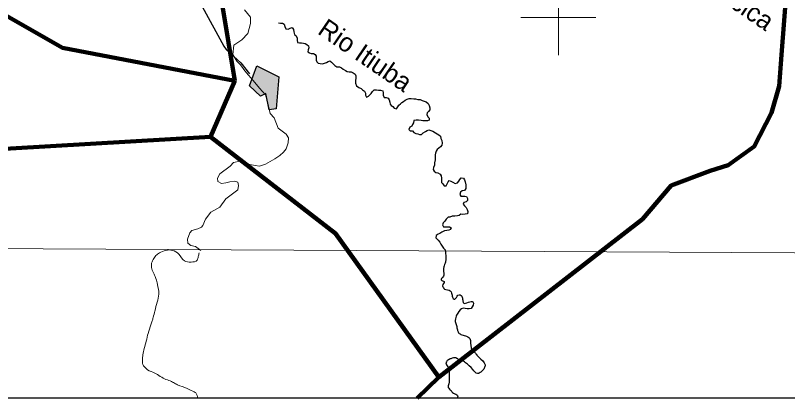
# Model space of a CAD drawing. Extents: x -1643653 to 4543381, y 1624270 to 13878484.
# Drawn here: x 735516 to 756116, y 8889723 to 8900056 of the extents above; entities that cross this region are included whole.
import ezdxf
from ezdxf.enums import TextEntityAlignment as Align

# ---------------------------------------------------------------- set-up
doc = ezdxf.new("R2010")
doc.units = 0
doc.header["$LTSCALE"] = 200
for name, color, linetype, lineweight in [('1', 7, 'Continuous', 13), ('12', 7, 'Continuous', 25), ('14', 7, 'Continuous', 13), ('2', 7, 'Continuous', 13), ('21', 7, 'Continuous', 25), ('24', 7, 'Continuous', 25), ('3', 7, 'Continuous', 13), ('57', 7, 'Continuous', 13), ('58', 7, 'Continuous', 13), ('60', 7, 'Continuous', 13), ('9', 7, 'Continuous', 90)]:
    doc.layers.add(name, color=color, linetype=linetype, lineweight=lineweight)
doc.layers.add('49', color=7, linetype='Continuous')

msp = doc.modelspace()

# ---------------------------------------------------------------- hatches: boundary and pattern name
at = {"layer": '21'}
msp.add_hatch(color=256, dxfattribs=at).paths.add_polyline_path([(741953.3, 8898708.5), (742539, 8898421), (742473.5, 8897565.2), (742282.6, 8897532.8), (742195.4, 8897971), (742053.9, 8897898.6), (741759, 8898176.9)])

# ---------------------------------------------------------------- linework, layer by layer
at = {"layer": '1'}
msp.add_lwpolyline([(564751.7, 8894587.5), (664411.9, 8894209.9), (791388.5, 8893536.2)], dxfattribs=at)
at = {"layer": '12'}
msp.add_lwpolyline([(746519.8, 8913147), (744583.5, 8912890.8), (744456, 8912865.6), (744221.3, 8912764.1), (744164.9, 8912662.3), (738981.9, 8906574.2), (738945.9, 8906472.4), (740401.6, 8900591.2), (740457, 8900407.7), (740497.3, 8900290.4), (741074.2, 8899240), (741140.1, 8899143.1), (741531, 8898790.9), (741761.4, 8898500.5)], dxfattribs=at)
at = {"layer": '14'}
msp.add_lwpolyline([(740463, 8893777.9), (740392, 8893831.3), (740315.8, 8893892.6), (740193.7, 8893918.3), (740112.4, 8893979.6), (740107.7, 8894081.4), (740164.3, 8894249.4), (740225.7, 8894315.6), (740378.7, 8894361.1), (740480.7, 8894401.7), (740516.6, 8894447.5), (740588.5, 8894620.5), (740731.8, 8894808.8), (740966.7, 8894940.8), (741130.5, 8895164.6), (741309.3, 8895291.6), (741447.2, 8895398.4), (741468, 8895515.5), (741453.1, 8895602.1), (741371.7, 8895632.8), (741234.1, 8895612.7), (741132.1, 8895587.4), (741009.7, 8895567.3), (740918.2, 8895623.5), (740908.4, 8895710.1), (740969.9, 8895827.1), (741245.8, 8896030.4), (741332.7, 8896127), (741501, 8896162.4), (741587.4, 8896116.4), (741658.7, 8896111.1), (741765.6, 8896075.3), (741908.1, 8896049.6), (742030.3, 8896034.1), (742188.4, 8896089.8), (742438.6, 8896232), (742566.2, 8896313.2), (742668.5, 8896409.8), (742740.1, 8896496.3), (742791.7, 8896659.2), (742802.3, 8896786.6), (742741.6, 8896883.4), (742523.1, 8897046.9), (742417.1, 8897322.1), (742310.6, 8897439.5), (742250.5, 8897714.7), (742190.2, 8897938.9), (742027.8, 8898112.4), (741855.3, 8898316.5), (741733.6, 8898464.5), (741637.2, 8898581.8), (741520.6, 8898734.9), (741424.2, 8898831.8), (741312.8, 8899015.4), (741344.3, 8899265), (741558.7, 8899402.1), (741717.3, 8899569.9), (741784.5, 8899839.8), (741790.2, 8900007.9), (741627.9, 8900201.8)], dxfattribs=at)
msp.add_spline([(740417.8, 8893718), (740395, 8893617.9), (740366.3, 8893527), (740201.3, 8893471.8), (740024.2, 8893508.9), (739877.2, 8893682.8), (739707.5, 8893786.1), (739358.5, 8893717.2), (739264.2, 8893644.1), (739189.2, 8893539.6), (739143.8, 8893408.5), (739155.2, 8893295.7), (739216.5, 8893150.5), (739263.3, 8893031.3), (739303.8, 8892876.6), (739340.8, 8892619.9), (739297.6, 8892401.9), (739233.3, 8892164.3), (739191.8, 8891997.3), (739163, 8891901.3), (739128.9, 8891800.4), (739054.6, 8891568.2), (739006.8, 8891365.7), (738954.1, 8891168.5), (738917.5, 8890996.2), (738902.9, 8890869.1), (738913.8, 8890741), (738932.9, 8890704.5), (739041.4, 8890598.4), (739232.1, 8890509.7), (739532.1, 8890340.4), (739683, 8890283.8), (739782.9, 8890223.9), (739838, 8890196.4), (740094.7, 8890100.1), (740245.1, 8890028.2), (740325, 8889979.3), (740376.2, 8889839.6), (740376.7, 8889836.8)], degree=3, dxfattribs=at)
at = {"layer": '2'}
for p, q in [((750000, 8899000), (750000, 8901000)), ((749000, 8900000), (751000, 8900000))]:
    msp.add_line(p, q, dxfattribs=at)
at = {"layer": '21'}
msp.add_lwpolyline([(741953.3, 8898708.5), (742539, 8898421), (742473.5, 8897565.2), (742282.6, 8897532.8), (742195.4, 8897971), (742053.9, 8897898.6), (741759, 8898176.9)], close=True, dxfattribs=at)
at = {"layer": '24'}
for points in [[(742537.4, 8899861.4), (742586, 8899849), (742636.8, 8899848.6), (742682.4, 8899822.9), (742702.3, 8899761.6), (742732.4, 8899695.2), (742793.4, 8899689.7), (742844.5, 8899719.9), (742900.5, 8899729.8), (742935.7, 8899678.6), (742945.5, 8899617.4), (742960.3, 8899551.1), (743005.8, 8899510.1), (743035.9, 8899453.8), (743035.5, 8899392.7), (743045.2, 8899331.5), (743096, 8899321), (743146.9, 8899320.7), (743197.7, 8899315.3), (743248.5, 8899304.8), (743294.1, 8899284.1), (743334.5, 8899243.1), (743344.3, 8899187), (743323.6, 8899136.2), (743318.2, 8899085.3), (743358.7, 8899054.4), (743409.4, 8899038.8), (743470.5, 8899038.4), (743516.1, 8899017.8), (743536.1, 8898971.8), (743535.8, 8898920.9), (743535.4, 8898864.8), (743560.5, 8898813.8), (743595.8, 8898777.9), (743646.7, 8898772.4), (743707.7, 8898767), (743763.7, 8898781.9), (743814.7, 8898796.8), (743855.6, 8898827.1), (743906.5, 8898842.1), (743947, 8898811.3), (743982.3, 8898770.3), (744032.9, 8898724.1), (744093.6, 8898683), (744159.7, 8898682.6), (744210.5, 8898661.9), (744261, 8898620.8), (744321.8, 8898584.7), (744367.5, 8898564.1), (744418.2, 8898548.5), (744474.2, 8898548.1), (744530, 8898527.4), (744580.6, 8898491.4), (744595.5, 8898440.3), (744595.1, 8898379.2), (744589.6, 8898318.1), (744584, 8898251.9), (744619.1, 8898180.4), (744679.8, 8898129.1), (744735.6, 8898103.3), (744776.1, 8898072.4), (744831.7, 8898031.3), (744851.8, 8897985.3), (744851.4, 8897929.3), (744881.5, 8897873.1), (744932.6, 8897903.3), (744968.4, 8897938.8), (745009.3, 8897974.2), (745040.2, 8898024.9), (745086.3, 8898070.4), (745147.3, 8898070.1), (745203.2, 8898064.6), (745259.2, 8898064.2), (745315, 8898043.5), (745329.9, 8897992.5), (745329.5, 8897931.3), (745354.5, 8897870.1), (745405.3, 8897869.7), (745456, 8897843.9), (745486.3, 8897803), (745506.2, 8897741.7), (745510.9, 8897690.8), (745541.2, 8897649.8), (745586.8, 8897624.1), (745622.1, 8897583.1), (745677.9, 8897562.4), (745713.9, 8897618.2), (745744.7, 8897663.8), (745785.6, 8897699.2), (745821.5, 8897734.6), (745872.5, 8897759.8), (745913.5, 8897795.2), (745964.5, 8897820.3), (746020.5, 8897835.2), (746076.5, 8897834.9), (746142.6, 8897834.4), (746193.4, 8897829), (746254.3, 8897808.3), (746315.3, 8897807.9), (746371.1, 8897782), (746421.9, 8897766.4)], [(746421.9, 8897766.4), (746477.7, 8897750.8), (746523.2, 8897709.8), (746553.3, 8897648.4), (746573.3, 8897592.3), (746567.8, 8897536.3), (746537, 8897495.7), (746501.2, 8897460.3), (746495.7, 8897409.4), (746520.8, 8897353.2), (746556.1, 8897312.2), (746549.6, 8897261.7), (746504.8, 8897246.3), (746443.7, 8897246.7), (746387.8, 8897247.1), (746336.9, 8897247.4), (746265.8, 8897258.1), (746209.9, 8897263.5), (746148.8, 8897248.6), (746133.1, 8897192.7), (746112.4, 8897141.9), (746091.8, 8897096.2), (746035.7, 8897076.2), (746009.8, 8897015.2), (746050.3, 8896979.3), (746106.2, 8896978.9), (746146.5, 8896927.7), (746197.2, 8896901.9), (746248, 8896891.4), (746298.8, 8896880.9), (746349.7, 8896880.6), (746390.6, 8896921.1), (746451.9, 8896956.3), (746497.9, 8896981.5), (746548.9, 8897006.6), (746599.6, 8896985.9), (746655.5, 8896970.3), (746726.3, 8896918.9), (746812.5, 8896872.5), (746857.9, 8896831.5), (746867.7, 8896770.3), (746892.7, 8896714.1), (746897.4, 8896647.8), (746891.9, 8896596.9), (746856, 8896546.2), (746815.1, 8896510.8), (746764, 8896480.6), (746738.2, 8896434.9), (746722.6, 8896384.1), (746717.2, 8896333.2), (746716.7, 8896261.9), (746711.2, 8896200.8), (746695.4, 8896119.4), (746695, 8896058.2), (746669.1, 8895997.3), (746663.6, 8895941.3), (746688.8, 8895895.3), (746729.2, 8895864.4), (746785.1, 8895853.9), (746845.9, 8895817.9), (746871, 8895771.9), (746880.8, 8895710.7), (746880.3, 8895649.5), (746885.1, 8895598.6), (746915.3, 8895557.6), (746955.7, 8895511.5), (747011.6, 8895511.2), (747037.4, 8895556.8), (747058.1, 8895612.8), (747088.9, 8895653.3), (747134.5, 8895632.6), (747185.2, 8895601.7), (747251.1, 8895565.7), (747312.2, 8895585.7), (747343.1, 8895631.3), (747373.9, 8895676.9), (747404.7, 8895717.5), (747465.7, 8895712), (747495.9, 8895671.1), (747515.9, 8895614.9), (747530.6, 8895538.4), (747530.2, 8895487.5), (747529.9, 8895436.5), (747493.9, 8895380.7), (747432.8, 8895370.9), (747391.9, 8895335.5), (747371.1, 8895274.5), (747401.3, 8895233.6), (747452.2, 8895228.2), (747503, 8895227.8), (747553.9, 8895222.4), (747573.8, 8895166.3), (747578.6, 8895115.3), (747537.7, 8895085), (747481.5, 8895059.9), (747460.9, 8895014.2), (747496.2, 8894978.3), (747541.7, 8894932.2), (747566.7, 8894876), (747586.7, 8894819.8), (747576.1, 8894763.8)], [(747576.1, 8894763.8), (747515, 8894748.9), (747453.9, 8894739.2), (747398, 8894749.7), (747357.1, 8894714.3), (747306.2, 8894704.4), (747234.9, 8894699.8), (747168.8, 8894695.1), (747107.6, 8894675.2), (747056.7, 8894670.4), (747005.5, 8894614.7), (746969.5, 8894569.1), (746928.5, 8894518.4), (746907.8, 8894462.5), (746937.9, 8894411.4), (746988.8, 8894411), (747039.7, 8894410.7), (747095.6, 8894415.4), (747141.2, 8894389.7), (747120.6, 8894344), (747074.7, 8894323.9), (747023.7, 8894314), (746962.6, 8894304.2), (746891.2, 8894274.1), (746840.1, 8894233.7), (746794.2, 8894213.6), (746738, 8894183.4), (746732.5, 8894117.2), (746793.1, 8894055.7), (746838.5, 8894004.5), (746868.6, 8893948.3), (746903.9, 8893897.1), (746934.1, 8893846), (746974.5, 8893805), (746979.5, 8893799.8)]]:
    msp.add_lwpolyline(points, dxfattribs=at)
msp.add_spline([(746979.5, 8893799.8), (746986.5, 8893472.8), (746946.2, 8893341.5), (746940.6, 8893178.3), (746921.6, 8893071.8), (746873.1, 8892996.9), (746953.2, 8892953.1), (746908.6, 8892842.4), (746932.2, 8892790.5), (746966.7, 8892753.5), (747117.8, 8892702), (747151.5, 8892644.6), (747178.3, 8892536.3), (747217.1, 8892478.7), (747258.7, 8892502.7), (747285.1, 8892527.3), (747322.8, 8892587.2), (747384.3, 8892595.2), (747442.4, 8892506.2), (747459.4, 8892408.6), (747468.7, 8892382.7), (747601.9, 8892403.3), (747719.4, 8892409.2), (747672.7, 8892237.3), (747458.7, 8892240.1), (747316.6, 8892112.5), (747261.6, 8891997.1), (747248.6, 8891915.8), (747270.3, 8891807.8), (747301.9, 8891689.2), (747324.6, 8891606.6), (747398.8, 8891542.6), (747519.9, 8891507.5), (747634.7, 8891436.9), (747660.9, 8891308.3), (747729.8, 8891091.3), (747764.6, 8891064.5), (747813.7, 8891011.6), (747877.2, 8890932.7), (748043.5, 8890727.4), (748025.2, 8890641.2), (747934.9, 8890537.3), (747847, 8890499.7), (747718, 8890601.5), (747520.5, 8890787.5), (747410.2, 8890842.6), (747379.7, 8890843.7), (747314.9, 8890886.9), (747203.8, 8890916.5), (747131.6, 8890893.7), (747085.1, 8890874.9), (747079.8, 8890870), (747064.4, 8890865.5), (747033, 8890841.1), (747000.5, 8890786.1), (747052.8, 8890677), (747089.2, 8890553.1), (747088.7, 8890389.7), (747077.9, 8890226.6), (747064.2, 8890125), (747137.8, 8890040.6), (747176.7, 8889988.1), (747236.8, 8889955.3), (747316.1, 8889891.1), (747301, 8889836.8)], degree=3, dxfattribs=at)
at = {"layer": '3', "lineweight": 25}
msp.add_lwpolyline([(563033.9, 9026438.8), (793061.1, 9026438.8), (793495.6, 8889836.8), (563468.3, 8889836.8)], close=True, dxfattribs=at)
at = {"layer": '57'}
for points in [[(724918, 8889836.8), (793495.6, 8889836.8), (793246.1, 8980523), (793207.5, 8980426.2)], [(714150.8, 8909075.2), (715793.9, 8908335.5), (718505, 8907595.7), (721708.9, 8906938.1), (724337.8, 8906773.8), (725488, 8906691.6), (726092.5, 8906203.6), (730163.4, 8902976.8), (733469.4, 8901085.6), (736775.3, 8899194.4), (741371.9, 8898310.2), (741034.6, 8900357.7)], [(741034.6, 8900357.7), (741371.9, 8898310.2), (736775.3, 8899194.4), (733469.4, 8901085.6), (730163.4, 8902976.8), (726092.5, 8906203.6), (725488, 8906691.6), (724337.8, 8906773.8), (721708.9, 8906938.1), (718505, 8907595.7), (715793.9, 8908335.5), (714150.8, 8909075.2)]]:
    msp.add_lwpolyline(points, dxfattribs=at)
at = {"layer": '58'}
msp.add_lwpolyline([(714150.8, 8909075.2), (715793.9, 8908335.5), (718505, 8907595.7), (721708.9, 8906938.1), (724337.8, 8906773.8), (725488, 8906691.6), (726092.5, 8906203.6), (730163.4, 8902976.8), (733469.4, 8901085.6), (736775.3, 8899194.4), (741371.9, 8898310.2), (741034.6, 8900357.7)], dxfattribs=at)
at = {"layer": '60', "lineweight": 25}
msp.add_spline([(814781, 9009175.5), (814787.2, 9009173.4), (814796.9, 9009173.4), (814799.4, 9009172.4), (814805.1, 9009174.5), (814805.6, 9009176.5), (814811.7, 9009179.5), (814811.7, 9009179.5), (814801.5, 9009181), (814790.7, 9009181.5), (814784.1, 9009183.1), (814777.4, 9009185.1), (814778.4, 9009175.5)], degree=3, dxfattribs=at)
at = {"layer": '9'}
for p, q in [((741371.9, 8898310.2), (736775.3, 8899194.4)), ((746801.1, 8890392.2), (746237.5, 8889836.8)), ((746801.1, 8890392.2), (746237.5, 8889836.8))]:
    msp.add_line(p, q, dxfattribs=at)
for points in [[(741371.9, 8898310.2), (736775.3, 8899194.4), (730163.4, 8902976.8), (725291.2, 8902898), (725401.2, 8914588.3), (719613.1, 8922670.1)], [(741371.9, 8898310.2), (741034.6, 8900357.7), (742318.1, 8903350.9), (743333.5, 8903255.5), (744802.2, 8904149.6), (746844.1, 8907956.8)], [(746808.9, 8890399.8), (752241.5, 8894614.2), (753009.4, 8895516.7), (754051.4, 8895909.3), (754534, 8896055.4), (755222.3, 8896553.7), (755686.3, 8897459.8), (755895.2, 8898166.4), (755953.2, 8899001.4), (756092.4, 8900844.6)], [(746808.9, 8890399.8), (752241.5, 8894614.2), (753009.4, 8895516.7), (754051.4, 8895909.3), (754534, 8896055.4), (755222.3, 8896553.7), (755686.3, 8897459.8), (755895.2, 8898166.4), (755953.2, 8899001.4), (756092.4, 8900844.6)], [(724638.9, 8891123.6), (729122.2, 8896139.1), (740717.5, 8896813.6), (741371.9, 8898310.2)], [(740717.5, 8896813.6), (744056.4, 8894231.8), (746808.9, 8890399.8), (746801.2, 8890392.2)], [(740717.5, 8896813.6), (744056.4, 8894231.8), (746808.9, 8890399.8), (746801.2, 8890392.2)]]:
    msp.add_lwpolyline(points, dxfattribs=at)

# ---------------------------------------------------------------- texts
at = {"layer": '49'}
for s, p in [('Rio Boacica', (754060.4, 8900632.7)), ('Rio Itiuba', (744712.7, 8898789.2))]:
    msp.add_text(s, height=500, rotation=325.606, dxfattribs=at).set_placement(p, align=Align.CENTER)

doc.saveas('drawing.dxf')
